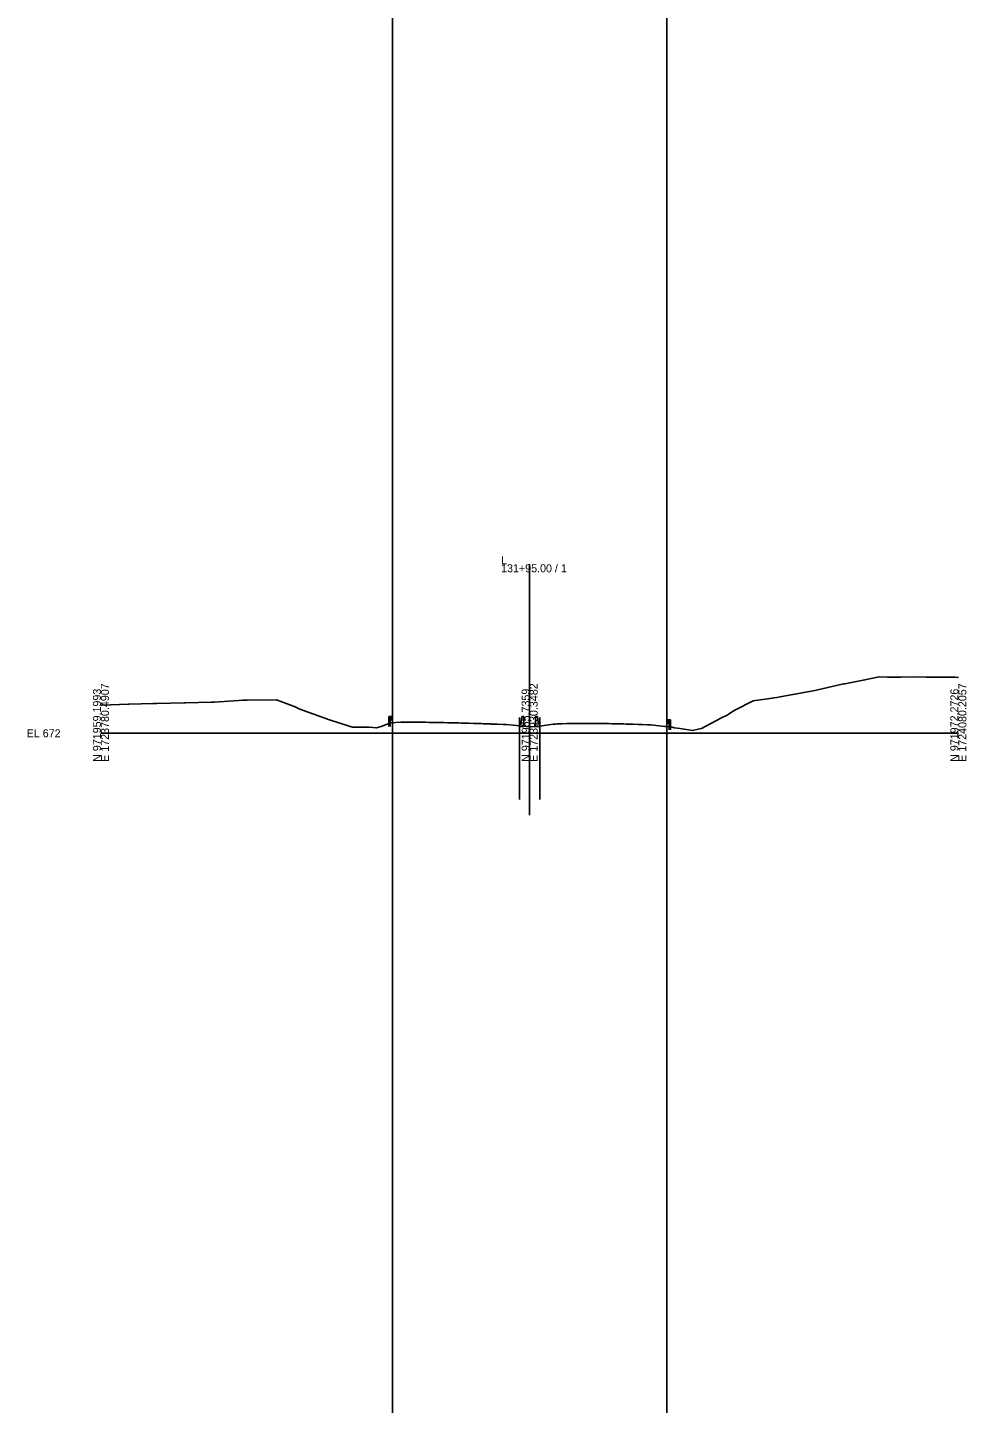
# Model space of a CAD drawing. Extents: x -26 to 303, y -29 to 15026.
# Drawn here: x -25.7 to 302.8, y 8765.4 to 9247 of the extents above; entities that cross this region are included whole.
import ezdxf

# ---------------------------------------------------------------- set-up
doc = ezdxf.new("R2010")
doc.units = 0
for name, color, linetype in [('Exist Cross Section Cell', 7, 'Continuous'), ('Exist XS Center Line Elevation Label', 7, 'Continuous'), ('Exist XS Ground Line', 7, 'Continuous'), ('Scratch_Level_0', 7, 'Continuous'), ('Typical Guardrail CELL', 7, 'Continuous'), ('Typical Median Barrier CELL', 7, 'Continuous')]:
    doc.layers.add(name, color=color, linetype=linetype)

msp = doc.modelspace()

# ---------------------------------------------------------------- linework, layer by layer
at = {"layer": 'Exist Cross Section Cell'}
for p, q in [((150, 9000), (150, 9059.15)), ((0, 9000), (150, 9000)), ((150, 9000), (300, 9000))]:
    msp.add_line(p, q, dxfattribs=at)
at = {"layer": 'Exist XS Ground Line'}
msp.add_lwpolyline([(0, 9009.82), (0.31, 9009.83), (9.53, 9010.14), (9.9, 9010.14), (18.32, 9010.39), (19.54, 9010.42), (29.08, 9010.67), (29.55, 9010.69), (38.67, 9010.89), (39.56, 9010.92), (48.26, 9011.5), (49.57, 9011.55), (51.12, 9011.62), (61.44, 9011.68), (67.94, 9009.2), (69.59, 9008.48), (77.03, 9005.73), (79.59, 9004.87), (86.79, 9002.54), (88.05, 9002.16), (89.02, 9002.15), (92.1, 9002.16), (92.92, 9002.15), (93.9, 9002.1), (96.36, 9001.94), (98.06, 9002.39), (101.28, 9003.67), (104.9, 9003.84), (105.95, 9003.87), (106.49, 9003.9), (108.04, 9003.91), (108.72, 9003.91), (111.35, 9003.89), (113.73, 9003.85), (114.79, 9003.83), (116.23, 9003.82), (117.41, 9003.8), (118.72, 9003.77), (119.94, 9003.74), (121.22, 9003.71), (122.32, 9003.69), (123.08, 9003.68), (123.71, 9003.66), (125.22, 9003.61), (126.21, 9003.58), (127.83, 9003.55), (128.7, 9003.53), (130.48, 9003.47), (131.22, 9003.45), (133.1, 9003.38), (133.72, 9003.36), (134.83, 9003.32), (135.71, 9003.28), (136.25, 9003.25), (136.7, 9003.24), (138.72, 9003.19), (140.76, 9003.12), (141.21, 9003.1), (141.79, 9003.06), (144.21, 9002.84), (150, 9002.27), (150.52, 9002.22), (152.66, 9002.43), (156.66, 9002.94), (158.21, 9003.14), (158.91, 9003.21), (159.49, 9003.27), (160.91, 9003.32), (161.26, 9003.33), (163.05, 9003.37), (164.28, 9003.4), (165.23, 9003.4), (166.28, 9003.4), (167.9, 9003.41), (168.77, 9003.42), (169.73, 9003.42), (171.29, 9003.43), (172.71, 9003.42), (173.78, 9003.42), (175.1, 9003.42), (176.28, 9003.41), (177.14, 9003.4), (177.55, 9003.39), (178.77, 9003.35), (179.88, 9003.32), (181.27, 9003.29), (182.78, 9003.25), (183.76, 9003.23), (184.66, 9003.2), (186.27, 9003.15), (188.02, 9003.1), (188.76, 9003.08), (189.35, 9003.06), (191.28, 9002.98), (192.27, 9002.92), (197.33, 9002.43), (197.91, 9002.37), (198.94, 9002.3), (199.45, 9002.24), (200.68, 9001.88), (202.7, 9001.63), (207, 9000.92), (208.97, 9001.42), (210.14, 9001.62), (216.94, 9005.29), (219.12, 9006.37), (219.76, 9006.77), (220.65, 9007.44), (221.78, 9008.08), (228.2, 9011.38), (234.89, 9012.29), (235.47, 9012.4), (236.44, 9012.56), (237.68, 9012.7), (249.78, 9015.01), (259.34, 9017.18), (259.9, 9017.26), (260.3, 9017.32), (267.33, 9018.69), (272.33, 9019.7), (275.17, 9019.68), (276.42, 9019.68), (279.89, 9019.67), (286.07, 9019.72), (288.72, 9019.67), (289.11, 9019.67), (289.88, 9019.68), (291.12, 9019.66), (291.49, 9019.66), (291.94, 9019.66), (293.2, 9019.65), (294.72, 9019.65), (296.6, 9019.62), (297.64, 9019.62), (298.91, 9019.59), (300, 9019.58)], dxfattribs=at)
at = {"layer": 'Scratch_Level_0'}
for p, q in [((102, 15009.56), (102, -28.7)), ((198, 15009.56), (198, -28.7)), ((146.46, 9005.5), (146.46, 8976.8)), ((153.54, 9005.5), (153.54, 8976.8)), ((150, 9000), (150, 8971.3)), ((150, 9000), (150, 8971.3))]:
    msp.add_line(p, q, dxfattribs=at)
at = {"layer": 'Typical Guardrail CELL'}
for p, q in [((101.18, 9005.92), (100.68, 9005.92)), ((100.68, 9005.92), (100.68, 9003.43)), ((101.18, 9005.92), (101.18, 9003.43)), ((101.18, 9005.92), (101.68, 9005.92)), ((101.68, 9005.92), (101.68, 9004.76)), ((101.68, 9005.92), (101.97, 9005.71)), ((101.68, 9005.38), (101.97, 9005.59)), ((101.68, 9005.34), (101.68, 9005.38)), ((101.68, 9005.34), (101.68, 9005.29)), ((101.68, 9005.29), (101.97, 9005.09)), ((101.18, 9003.43), (100.68, 9003.43)), ((100.68, 9003.43), (100.68, 9002.42)), ((101.18, 9004.76), (101.68, 9004.76)), ((101.18, 9003.43), (101.18, 9002.42)), ((101.68, 9004.76), (101.97, 9004.96)), ((198.32, 9004.74), (198.03, 9004.54)), ((198.32, 9004.21), (198.03, 9004.41)), ((198.32, 9004.11), (198.03, 9003.91)), ((198.32, 9003.58), (198.03, 9003.78)), ((198.82, 9004.74), (198.32, 9004.74)), ((198.32, 9004.74), (198.32, 9003.58)), ((198.32, 9004.16), (198.32, 9004.21)), ((198.32, 9004.16), (198.32, 9004.11)), ((198.82, 9003.58), (198.32, 9003.58)), ((198.82, 9004.74), (198.82, 9002.25)), ((198.82, 9004.74), (199.32, 9004.74)), ((198.82, 9002.25), (199.32, 9002.25)), ((198.82, 9002.25), (198.82, 9001.24)), ((199.32, 9004.74), (199.32, 9002.25)), ((199.32, 9002.25), (199.32, 9001.24))]:
    msp.add_line(p, q, dxfattribs=at)
for centre, start, end in [((101.92, 9005.65), 304.9888, 54.997), ((101.92, 9005.02), 304.9634, 54.9941), ((198.08, 9004.47), 125.003, 235.0112), ((198.08, 9003.85), 125.0059, 235.0366)]:
    msp.add_arc(centre, 0.0776, start, end, dxfattribs=at)
at = {"layer": 'Typical Median Barrier CELL'}
for p, q in [((147.07, 9003.86), (147.29, 9005.82)), ((147.29, 9005.82), (147.96, 9005.82)), ((147.96, 9005.82), (147.96, 9002.4)), ((152.71, 9005.82), (152.04, 9005.82)), ((152.04, 9005.82), (152.04, 9002.4)), ((152.93, 9003.86), (152.71, 9005.82)), ((146.46, 9002.82), (146.92, 9003.47)), ((146.46, 9002.4), (146.46, 9002.82)), ((147.96, 9002.4), (146.46, 9002.4)), ((152.04, 9002.4), (153.54, 9002.4)), ((153.54, 9002.82), (153.08, 9003.47)), ((153.54, 9002.4), (153.54, 9002.82))]:
    msp.add_line(p, q, dxfattribs=at)
for centre, start, end in [((146.24, 9003.95), 325.0039, 353.9447), ((153.76, 9003.95), 186.0553, 214.9961)]:
    msp.add_arc(centre, 0.833, start, end, dxfattribs=at)

# ---------------------------------------------------------------- texts
at = {"layer": 'Exist Cross Section Cell'}
for s, p in [('131+95.00 / 1', (140, 9056.35)), ('L', (140, 9059.15)), ('EL 672', (-26, 8998.6))]:
    msp.add_text(s, height=2.8, dxfattribs=at).set_placement(p)
for s, p in [('N 971959.1993', (0, 8990)), ('E 1723780.4907', (2.8, 8990)), ('N 971965.7359', (150, 8990)), ('E 1723930.3482', (152.8, 8990)), ('N 971972.2726', (300, 8990)), ('E 1724080.2057', (302.8, 8990))]:
    msp.add_text(s, height=2.8, rotation=90, dxfattribs=at).set_placement(p)
at = {"layer": 'Exist XS Center Line Elevation Label'}
msp.add_text('674.27', height=0.18, dxfattribs=at).set_placement((149.61, 9001.78))

doc.saveas('drawing.dxf')
